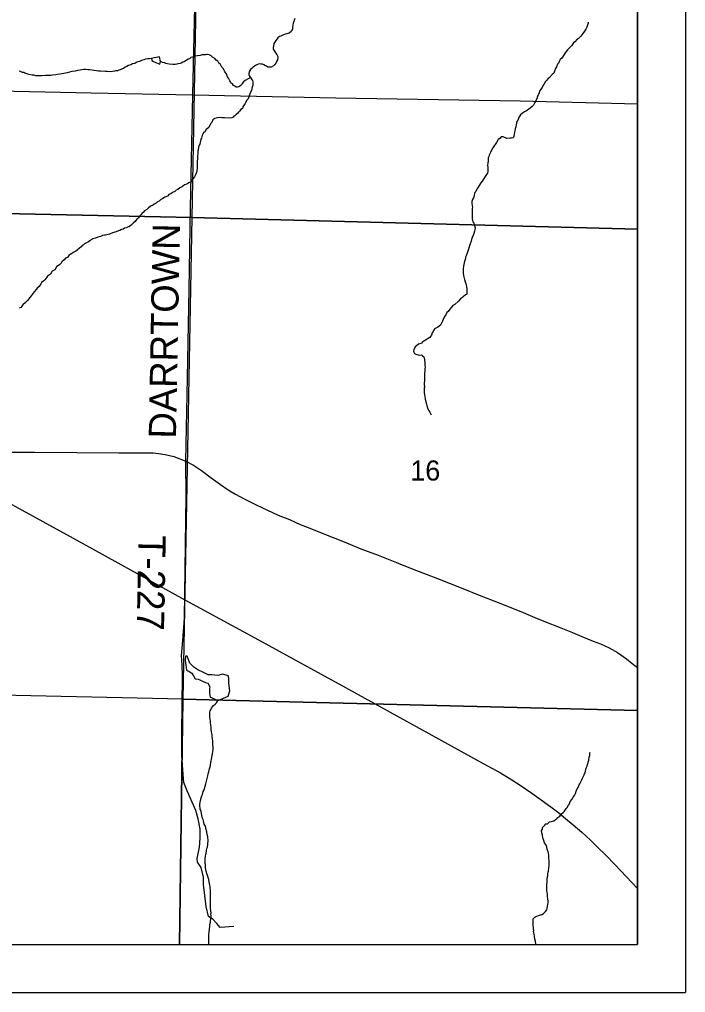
# Model space of a CAD drawing. Extents: x 0 to 34, y 0 to 22.
# Drawn here: x 7.614 to 9, y 14 to 16.024 of the extents above; entities that cross this region are included whole.
import ezdxf

# ---------------------------------------------------------------- set-up
doc = ezdxf.new("R2010")
doc.units = 0
for name, color, linetype in [('Default', 7, 'Continuous'), ('GM_X_County_Road', 7, 'Continuous'), ('GM_X_Minor_River', 7, 'Continuous'), ('GM_X_Rail_Line', 7, 'Continuous'), ('GM_X_Section', 7, 'Continuous'), ('GM_X_Section_Text', 7, 'Continuous'), ('GM_X_State_Route', 7, 'Continuous'), ('GM_X_Township_Road', 7, 'Continuous'), ('GM_X_Township_Road_Text', 7, 'Continuous'), ('SH_Data', 7, 'Continuous')]:
    doc.layers.add(name, color=color, linetype=linetype)

msp = doc.modelspace()

# ---------------------------------------------------------------- linework, layer by layer
at = {"layer": 'Default'}
for points in [[(5.898, 14.1), (8.9, 14.1), (8.9, 17.6104), (8.0065, 17.6245), (7.0308, 17.6406), (6.9889, 17.643), (5.9893, 17.6676), (5.9888, 17.6433), (5.9796, 17.2537), (5.9756, 17.0812), (5.9658, 16.6637), (5.9579, 16.0817), (5.9546, 15.9939), (5.9496, 15.8622), (5.9475, 15.8049), (5.945, 15.7379), (5.9423, 15.6675), (5.9419, 15.65), (5.9251, 14.9951), (5.9162, 14.6505)], [(8.9, 15.5877), (8.9, 16.5944), (7.9916, 16.6192), (7.9729, 15.6119)], [(8.9, 14.587), (8.9, 15.5877), (7.9729, 15.6119), (7.9542, 14.61)], [(6.9613, 14.1), (7.9469, 14.1), (7.9542, 14.61), (6.9732, 14.6315)], [(7.9469, 14.1), (8.9, 14.1), (8.9, 14.587), (7.9542, 14.61)]]:
    msp.add_lwpolyline(points, close=True, dxfattribs=at)
at = {"layer": 'GM_X_County_Road'}
msp.add_lwpolyline([(6.7323, 15.8976), (6.7874, 15.896), (6.8287, 15.8947), (6.9536, 15.8914), (6.9998, 15.8902), (7.2608, 15.882), (7.474, 15.8776), (7.7629, 15.8716), (7.9749, 15.8672), (8.2725, 15.8609), (8.656, 15.8552), (8.9, 15.8485)], dxfattribs=at)
at = {"layer": 'GM_X_Minor_River'}
for points in [[(8.1871, 16.0264), (8.1855, 16.023), (8.1847, 16.0196), (8.1834, 16.0162), (8.183, 16.0121), (8.1821, 16.0083), (8.182, 16.0041), (8.1804, 16.0019), (8.1792, 15.9992), (8.1754, 15.9959), (8.1727, 15.9948), (8.1704, 15.9941), (8.1669, 15.9935), (8.1635, 15.992), (8.1581, 15.9891), (8.155, 15.9884), (8.1519, 15.9862), (8.1504, 15.984), (8.1473, 15.9807), (8.1456, 15.9769), (8.1433, 15.9743), (8.1424, 15.969), (8.142, 15.9656), (8.1419, 15.9626), (8.1434, 15.9602), (8.1444, 15.9579), (8.147, 15.9544), (8.1492, 15.951), (8.1514, 15.9471), (8.1517, 15.9448), (8.1509, 15.9399), (8.1489, 15.9369), (8.1477, 15.9332), (8.1453, 15.9302), (8.1426, 15.9276), (8.138, 15.925), (8.1357, 15.9247), (8.1311, 15.9252), (8.1281, 15.9272), (8.1259, 15.9276), (8.1225, 15.9296), (8.1199, 15.9312), (8.1165, 15.9313), (8.113, 15.9317), (8.1096, 15.9307), (8.1054, 15.9285), (8.103, 15.9267), (8.1, 15.9252), (8.0972, 15.9219), (8.0949, 15.92), (8.0929, 15.9167), (8.0913, 15.9118), (8.0912, 15.9095), (8.0927, 15.906), (8.0949, 15.9033), (8.0971, 15.9002), (8.0986, 15.8975), (8.0992, 15.8941), (8.0995, 15.8903), (8.0995, 15.8876), (8.099, 15.8853), (8.0978, 15.8812), (8.0969, 15.8763), (8.0942, 15.8718), (8.0921, 15.8654), (8.0901, 15.8593), (8.0866, 15.8553), (8.085, 15.8523), (8.0838, 15.8492), (8.0818, 15.8466), (8.0787, 15.8422), (8.0782, 15.8391), (8.0747, 15.8366), (8.0716, 15.8332), (8.07, 15.831), (8.0673, 15.8288), (8.0646, 15.8265), (8.0623, 15.8239), (8.06, 15.8229), (8.0584, 15.8206), (8.0557, 15.8195), (8.0519, 15.8189), (8.0409, 15.8192), (8.0378, 15.8196), (8.0348, 15.8197), (8.0317, 15.8201), (8.026, 15.8195), (8.0203, 15.8181), (8.0164, 15.8152), (8.014, 15.8099), (8.0113, 15.807), (8.0077, 15.7991), (8.0023, 15.7954), (7.9995, 15.7905), (7.9968, 15.7891), (7.9956, 15.7853), (7.994, 15.7827), (7.9927, 15.7774), (7.9915, 15.7752)], [(8.7976, 16.0185), (8.7976, 16.0162), (8.7955, 16.0102), (8.7944, 16.0079), (8.7927, 16.0042), (8.79, 15.9997), (8.7865, 15.9952), (8.7845, 15.9922), (8.7818, 15.9896), (8.7771, 15.9844), (8.7748, 15.9829), (8.7697, 15.9774), (8.7666, 15.9756), (8.7627, 15.9696), (8.7545, 15.9607), (8.7498, 15.9547), (8.7474, 15.9513), (8.7427, 15.9435), (8.7392, 15.9409), (8.7376, 15.9383), (8.736, 15.9341), (8.7333, 15.9312), (8.7312, 15.9255), (8.7292, 15.9221), (8.7276, 15.9165), (8.726, 15.9127), (8.7225, 15.9098), (8.7163, 15.9027), (8.7139, 15.9012), (8.7104, 15.8975), (8.7089, 15.8953), (8.7049, 15.8889), (8.7033, 15.8863), (8.7017, 15.8826), (8.697, 15.8762), (8.6954, 15.8717), (8.6934, 15.8668), (8.6914, 15.8631), (8.6909, 15.8608), (8.6882, 15.8552), (8.6858, 15.8499), (8.6838, 15.8461), (8.681, 15.8428), (8.6768, 15.8395), (8.6714, 15.8354), (8.669, 15.8344), (8.6648, 15.8318), (8.6609, 15.8292), (8.6563, 15.8255), (8.6535, 15.8218), (8.6507, 15.8147), (8.6491, 15.8117), (8.6479, 15.8087), (8.6475, 15.8052), (8.6466, 15.8007), (8.6457, 15.7965), (8.6449, 15.7928), (8.6444, 15.7897), (8.6436, 15.7852), (8.6427, 15.7814), (8.6411, 15.778), (8.6377, 15.777), (8.635, 15.7771), (8.6282, 15.7768), (8.6202, 15.7797), (8.6161, 15.7802), (8.6133, 15.7768), (8.6099, 15.7743), (8.6063, 15.7679), (8.5992, 15.7574), (8.596, 15.7522), (8.5944, 15.7473), (8.5924, 15.7447), (8.5912, 15.742), (8.5904, 15.739), (8.5896, 15.7364), (8.5891, 15.7322), (8.5891, 15.7299), (8.5886, 15.725), (8.5881, 15.7212), (8.5884, 15.7163), (8.5887, 15.7132), (8.5886, 15.7087), (8.5877, 15.7045), (8.5861, 15.7019), (8.5818, 15.6952), (8.5779, 15.6899), (8.5727, 15.6821), (8.5684, 15.6754), (8.5661, 15.6724), (8.5633, 15.6664), (8.5613, 15.6641), (8.5609, 15.6619), (8.56, 15.6581), (8.5588, 15.6532), (8.5568, 15.6498), (8.5552, 15.6457), (8.5551, 15.6422), (8.5561, 15.6365), (8.5564, 15.6335), (8.556, 15.6308)], [(8.0949, 15.9033), (8.0834, 15.8975), (8.0802, 15.8942), (8.0775, 15.8912), (8.0759, 15.8882), (8.0728, 15.8856), (8.0701, 15.8838), (8.0674, 15.8835), (8.0652, 15.8835), (8.0622, 15.8855), (8.0595, 15.8867), (8.057, 15.8906), (8.0547, 15.8918), (8.0532, 15.8945), (8.0514, 15.8968), (8.0492, 15.9022), (8.047, 15.9049), (8.0445, 15.9114), (8.0412, 15.9149), (8.0383, 15.9218), (8.0349, 15.9246), (8.0324, 15.9303), (8.029, 15.9331), (8.0265, 15.9373), (8.0231, 15.9393), (8.0205, 15.9431), (8.0153, 15.9459), (8.013, 15.9487), (8.0089, 15.9503), (8.0055, 15.9511), (8.0032, 15.9512), (8.0009, 15.9509), (7.9986, 15.9509), (7.9941, 15.9503), (7.9902, 15.9492), (7.9841, 15.9482), (7.9799, 15.948), (7.9776, 15.9472), (7.9742, 15.9458), (7.9707, 15.9448), (7.968, 15.9425), (7.965, 15.9415), (7.9622, 15.9393), (7.9592, 15.9378), (7.9565, 15.936), (7.9538, 15.9353), (7.9503, 15.9335), (7.948, 15.9328), (7.9438, 15.9317), (7.9415, 15.9314), (7.9381, 15.9308), (7.9358, 15.9308), (7.9331, 15.9305), (7.9256, 15.9314), (7.9221, 15.9319), (7.9184, 15.9328), (7.9157, 15.9336), (7.9116, 15.9344), (7.9089, 15.936), (7.9073, 15.9364)], [(7.8885, 15.9431), (7.8844, 15.9423), (7.8809, 15.942), (7.8764, 15.9414), (7.8729, 15.94), (7.8679, 15.9389), (7.8637, 15.9364), (7.858, 15.9354), (7.8537, 15.9328), (7.8488, 15.9322), (7.8457, 15.93), (7.8411, 15.9286), (7.8376, 15.926), (7.8338, 15.9246), (7.8303, 15.922), (7.8264, 15.9206), (7.8237, 15.9191), (7.8207, 15.9185), (7.8176, 15.9174), (7.8138, 15.9171), (7.8115, 15.9164), (7.8077, 15.9157), (7.8035, 15.9155), (7.7963, 15.9156), (7.7921, 15.9161), (7.7826, 15.9164), (7.7781, 15.9169), (7.7739, 15.9173), (7.7686, 15.9179), (7.7652, 15.9187), (7.7599, 15.9192), (7.7561, 15.9197), (7.7511, 15.9198), (7.7477, 15.9199)], [(7.9073, 15.9364), (7.9052, 15.9463), (7.8987, 15.9452), (7.8942, 15.9446), (7.8885, 15.9431), (7.8891, 15.9389), (7.8929, 15.9366)], [(7.8929, 15.9366), (7.8989, 15.9338), (7.9061, 15.9314), (7.9073, 15.9364)], [(7.7477, 15.9199), (7.7435, 15.9196), (7.7401, 15.9189), (7.7344, 15.9183), (7.7297, 15.9165), (7.7229, 15.9156), (7.7133, 15.9131), (7.7095, 15.9125), (7.7026, 15.9111), (7.6988, 15.9105), (7.6927, 15.9095), (7.6893, 15.9092), (7.6828, 15.9082), (7.6794, 15.9079), (7.671, 15.9077), (7.6683, 15.9074), (7.6607, 15.9072), (7.6573, 15.9069), (7.6482, 15.9072), (7.644, 15.908), (7.6402, 15.9085), (7.6372, 15.9089), (7.6334, 15.9098), (7.6289, 15.9114), (7.6251, 15.9123), (7.6228, 15.9135), (7.6202, 15.9139), (7.6164, 15.9159), (7.613, 15.9164)], [(7.9915, 15.7752), (7.989, 15.765), (7.9878, 15.7627), (7.9866, 15.7582), (7.9857, 15.7521), (7.9853, 15.7499), (7.9848, 15.7457), (7.9846, 15.7388), (7.9841, 15.7339), (7.984, 15.7297), (7.9836, 15.7271), (7.9835, 15.7233), (7.9838, 15.7206), (7.9837, 15.7134), (7.9832, 15.7104), (7.9823, 15.7058), (7.9811, 15.7021), (7.9783, 15.6968), (7.9748, 15.6923), (7.9709, 15.6867), (7.9663, 15.6846), (7.9624, 15.6816), (7.9574, 15.6799), (7.9528, 15.6762), (7.9474, 15.674), (7.9435, 15.6703), (7.94, 15.6689), (7.9369, 15.6663), (7.9323, 15.6645), (7.9288, 15.6616), (7.925, 15.6601), (7.9219, 15.6568), (7.9161, 15.6547), (7.9119, 15.651), (7.908, 15.6495), (7.9045, 15.6462), (7.9011, 15.6448), (7.8984, 15.6418), (7.8941, 15.64), (7.891, 15.6374), (7.8883, 15.6367), (7.8822, 15.6323), (7.8787, 15.6286), (7.874, 15.6261), (7.8713, 15.6227), (7.869, 15.6212), (7.8674, 15.6182), (7.8643, 15.6157), (7.8615, 15.6108), (7.8576, 15.6082), (7.8545, 15.6037), (7.8502, 15.6004), (7.8463, 15.5963), (7.8436, 15.5945), (7.8413, 15.5931), (7.8386, 15.592), (7.8359, 15.5905), (7.8325, 15.5899), (7.8294, 15.588), (7.826, 15.587), (7.8229, 15.5855), (7.8202, 15.5848), (7.8148, 15.5823), (7.8072, 15.5802), (7.801, 15.5773), (7.7957, 15.5763), (7.793, 15.5756), (7.7907, 15.5753), (7.7865, 15.5746), (7.7823, 15.5725), (7.7773, 15.5715), (7.7723, 15.5689), (7.7666, 15.5679), (7.7604, 15.5639), (7.7577, 15.5617), (7.7492, 15.5573), (7.7469, 15.5555), (7.7446, 15.554), (7.7422, 15.551), (7.7388, 15.5481), (7.7341, 15.5444), (7.7314, 15.5422), (7.7283, 15.5411), (7.726, 15.5397), (7.7225, 15.5367), (7.7198, 15.5356), (7.7164, 15.5331), (7.7136, 15.5293), (7.7098, 15.5275), (7.707, 15.5238), (7.7024, 15.5201), (7.7008, 15.5175), (7.698, 15.5141), (7.6911, 15.5097), (7.6872, 15.5034), (7.6818, 15.5005), (7.6782, 15.4941), (7.6724, 15.4901), (7.6712, 15.4878), (7.6669, 15.4822), (7.6646, 15.4808)], [(8.556, 15.6308), (8.5563, 15.627), (8.556, 15.6141), (8.5562, 15.6092), (8.5569, 15.6061), (8.5576, 15.6034), (8.5591, 15.6003), (8.5602, 15.5977), (8.5609, 15.5954), (8.5619, 15.5904), (8.5614, 15.5866), (8.561, 15.5836), (8.5597, 15.579), (8.5581, 15.5749), (8.5569, 15.5727), (8.5561, 15.5704), (8.5549, 15.5662), (8.5537, 15.5632), (8.552, 15.5572), (8.55, 15.5512), (8.5475, 15.5444), (8.5463, 15.5399), (8.5438, 15.5327), (8.5422, 15.5297), (8.5418, 15.527), (8.5409, 15.5229), (8.5393, 15.5176), (8.5389, 15.5146), (8.538, 15.5112), (8.5375, 15.5055), (8.5373, 15.4968), (8.5379, 15.4914), (8.5383, 15.4891), (8.54, 15.4834), (8.5414, 15.4784), (8.5432, 15.4727), (8.5442, 15.4673), (8.5449, 15.4635), (8.5449, 15.4612), (8.5451, 15.4574), (8.5451, 15.4551), (8.5447, 15.4529), (8.5423, 15.451), (8.5373, 15.447), (8.5338, 15.4444), (8.5315, 15.4429), (8.5272, 15.4381), (8.5198, 15.4314), (8.516, 15.4292), (8.5132, 15.4255), (8.5097, 15.4218), (8.5062, 15.4166), (8.5035, 15.4144), (8.5015, 15.4098), (8.4987, 15.4061), (8.4959, 15.3997), (8.4939, 15.3964), (8.4919, 15.3922), (8.4903, 15.3885), (8.4872, 15.3859), (8.4837, 15.3833), (8.4807, 15.3822), (8.4784, 15.3815), (8.4752, 15.3771), (8.4748, 15.3748), (8.4728, 15.3722), (8.4712, 15.3677), (8.4693, 15.365), (8.4677, 15.3628), (8.4646, 15.3602), (8.4623, 15.3591), (8.4588, 15.3569), (8.4557, 15.3547), (8.4526, 15.3537), (8.4503, 15.3511), (8.4468, 15.3496), (8.4445, 15.3485), (8.4403, 15.3452), (8.4376, 15.343), (8.4344, 15.337), (8.4339, 15.3344), (8.4343, 15.3321), (8.4361, 15.3294), (8.4384, 15.3278), (8.441, 15.327), (8.4433, 15.3262), (8.4459, 15.3261), (8.4505, 15.3264), (8.4527, 15.3244), (8.4557, 15.3224), (8.4571, 15.3167), (8.4571, 15.3144), (8.4578, 15.3114), (8.4576, 15.3045), (8.4579, 15.3015), (8.4574, 15.2973), (8.4573, 15.2935), (8.4568, 15.2867), (8.4565, 15.2745), (8.4563, 15.2658), (8.4566, 15.2593)], [(7.6646, 15.4808), (7.6599, 15.4767), (7.6583, 15.4745), (7.6548, 15.4688), (7.6505, 15.4655), (7.6497, 15.4629), (7.6446, 15.4573), (7.6423, 15.4551), (7.6384, 15.4495), (7.6356, 15.4461), (7.6305, 15.4394), (7.6266, 15.4353), (7.6212, 15.4302), (7.6169, 15.4253), (7.6131, 15.4235)], [(8.4566, 15.2593), (8.4561, 15.257), (8.4564, 15.2521), (8.4563, 15.2472), (8.4566, 15.2441), (8.4573, 15.2399), (8.4583, 15.2342), (8.4593, 15.2292), (8.46, 15.2262), (8.4607, 15.2239), (8.4614, 15.2212), (8.4628, 15.2166), (8.465, 15.2116), (8.4683, 15.2062), (8.4705, 15.2019)], [(8.0273, 14.6077), (8.0481, 14.6164), (8.0517, 14.6274), (8.0494, 14.6438), (8.0496, 14.654), (8.0482, 14.659), (8.0369, 14.6623), (8.0266, 14.6598), (8.0141, 14.6609), (8.0068, 14.6606), (7.9952, 14.6666), (7.985, 14.6713), (7.9768, 14.6768), (7.9686, 14.6854), (7.9653, 14.6942), (7.9632, 14.6999), (7.9594, 14.6996), (7.9588, 14.6909), (7.9598, 14.6814), (7.9618, 14.6707), (7.9671, 14.6675), (7.9727, 14.6644), (7.976, 14.6586), (7.9793, 14.6528)], [(7.9793, 14.6528), (7.9857, 14.6516), (7.9895, 14.6503), (7.9963, 14.6472), (8.0008, 14.6452), (8.0061, 14.6432), (8.0101, 14.6362), (8.0093, 14.6317), (8.0095, 14.6229), (8.0108, 14.6142), (8.0146, 14.6129), (8.0247, 14.6082), (8.0273, 14.6077)], [(8.0115, 14.4729), (8.0124, 14.4789), (8.0128, 14.4812), (8.0137, 14.4854), (8.0145, 14.4888), (8.015, 14.4937), (8.0158, 14.496), (8.0163, 14.5016), (8.0168, 14.5054), (8.0169, 14.5111), (8.0166, 14.5142), (8.0164, 14.5195), (8.0161, 14.5241), (8.0158, 14.5271), (8.0152, 14.534), (8.0149, 14.5363), (8.0142, 14.5389), (8.0135, 14.5431), (8.0128, 14.5466), (8.0125, 14.5504), (8.0123, 14.5572), (8.0116, 14.5603), (8.0113, 14.5637), (8.0107, 14.5694), (8.0104, 14.5725), (8.01, 14.5748), (8.0102, 14.5831), (8.011, 14.5858), (8.0119, 14.588), (8.0138, 14.5918), (8.0178, 14.597), (8.0213, 14.6), (8.024, 14.6029), (8.026, 14.6059), (8.0273, 14.6077)], [(8.7636, 14.4013), (8.766, 14.4062), (8.7688, 14.4099), (8.77, 14.4129), (8.7716, 14.4155), (8.7724, 14.4186), (8.7744, 14.4235), (8.7768, 14.4268), (8.7784, 14.4317), (8.7803, 14.4343), (8.7815, 14.437), (8.7828, 14.44), (8.784, 14.4422), (8.7848, 14.4445), (8.786, 14.4475), (8.7888, 14.4527), (8.7896, 14.455), (8.7908, 14.4573), (8.7916, 14.4603), (8.7933, 14.4667), (8.7953, 14.4708), (8.7957, 14.4742), (8.7965, 14.4765), (8.7978, 14.481), (8.7986, 14.4833), (8.7995, 14.4894), (8.8007, 14.4931), (8.8008, 14.4977), (8.8012, 14.5)], [(8.0079, 14.1), (8.0081, 14.1092), (8.0079, 14.1172), (8.008, 14.1206), (8.0085, 14.1259), (8.0094, 14.1309), (8.0099, 14.1388), (8.0104, 14.1418), (8.0112, 14.1464), (8.0122, 14.1555), (8.0127, 14.1593), (8.0124, 14.1635), (8.0125, 14.1661), (8.0121, 14.1692), (8.0115, 14.176), (8.0112, 14.1795), (8.0115, 14.1901), (8.0112, 14.1931), (8.0115, 14.2083), (8.0112, 14.2106), (8.0113, 14.2137), (8.011, 14.2167), (8.0107, 14.2205), (8.0103, 14.2236), (8.0097, 14.2266), (8.0086, 14.2304), (8.0079, 14.235), (8.0065, 14.2396), (8.0055, 14.2434), (8.004, 14.2473), (8.0023, 14.2523), (8.0016, 14.2557), (8.0009, 14.2595), (8.0007, 14.2664), (8.0004, 14.2687), (8.0001, 14.2728), (8.0006, 14.2778), (8.0011, 14.2842), (8.0015, 14.2869), (8.0024, 14.2895), (8.0029, 14.2952), (8.0041, 14.2994), (8.0049, 14.3024), (8.0058, 14.3077), (8.0059, 14.31), (8.0064, 14.3156), (8.0058, 14.324), (8.0048, 14.3286), (8.0041, 14.3343), (8.0023, 14.3389), (8.001, 14.3458), (7.998, 14.3504), (7.9967, 14.3573), (7.996, 14.36), (7.9942, 14.3638), (7.9929, 14.373), (7.9918, 14.3768), (7.99, 14.3814), (7.9894, 14.3894), (7.9891, 14.3921), (7.9896, 14.3951), (7.9904, 14.3997), (7.9929, 14.4068), (7.9933, 14.4091), (7.9945, 14.4117), (7.9962, 14.4181), (7.9982, 14.4219), (8.0002, 14.4294), (8.0015, 14.4344), (8.0028, 14.44), (8.004, 14.4427), (8.0061, 14.451), (8.0065, 14.4548), (8.0081, 14.4589), (8.009, 14.4631), (8.0107, 14.4695), (8.0115, 14.4729)], [(8.6888, 14.1), (8.6887, 14.1006), (8.688, 14.1067), (8.6866, 14.1113), (8.686, 14.117), (8.6849, 14.1212), (8.6846, 14.1243), (8.6839, 14.1269), (8.684, 14.1292), (8.6833, 14.1327), (8.6831, 14.1414), (8.6828, 14.1441), (8.6829, 14.1475), (8.6826, 14.1509), (8.683, 14.1532), (8.6865, 14.1569), (8.6888, 14.1584), (8.6927, 14.1598), (8.6958, 14.1612), (8.6984, 14.1615), (8.7007, 14.1623), (8.7042, 14.1644), (8.7085, 14.1685), (8.7112, 14.1719), (8.712, 14.1745), (8.7129, 14.1794), (8.7134, 14.1832), (8.7138, 14.1874), (8.7139, 14.19), (8.7136, 14.195), (8.713, 14.2), (8.7124, 14.2053), (8.7117, 14.2084), (8.7114, 14.2122), (8.7114, 14.2152), (8.7112, 14.2194), (8.7116, 14.2224), (8.7118, 14.2319), (8.7123, 14.238), (8.7132, 14.2429), (8.7137, 14.2475), (8.7141, 14.2501), (8.7146, 14.2524), (8.7155, 14.2592), (8.716, 14.2634), (8.7161, 14.2687), (8.7159, 14.2755), (8.7155, 14.2782), (8.7153, 14.282), (8.7153, 14.2858), (8.7147, 14.2896), (8.714, 14.2927), (8.7122, 14.298), (8.7105, 14.3061), (8.7086, 14.3084), (8.7064, 14.3111), (8.705, 14.3165), (8.7028, 14.3215), (8.7022, 14.3276), (8.7008, 14.3318), (8.7005, 14.336), (8.7021, 14.3397), (8.7026, 14.3435), (8.7073, 14.348), (8.7096, 14.3506), (8.7127, 14.3512), (8.7169, 14.3549), (8.7211, 14.356), (8.7257, 14.3574), (8.7292, 14.3596), (8.7323, 14.3614), (8.7342, 14.364), (8.7385, 14.3666), (8.7409, 14.3707), (8.7451, 14.3744), (8.7479, 14.3774), (8.7514, 14.3826), (8.7534, 14.3848), (8.7565, 14.3897), (8.7585, 14.3927), (8.7601, 14.3976), (8.7636, 14.4013)]]:
    msp.add_lwpolyline(points, dxfattribs=at)
at = {"layer": 'GM_X_Rail_Line'}
msp.add_lwpolyline([(7.5481, 15.0419), (7.6194, 15.0032), (7.7191, 14.9486), (7.9583, 14.8172), (8.1034, 14.7375), (8.2925, 14.6342), (8.5789, 14.4766), (8.6146, 14.4567), (8.6386, 14.4421), (8.6581, 14.4297), (8.6798, 14.415), (8.7041, 14.3977), (8.7227, 14.3839), (8.7362, 14.3737), (8.7502, 14.3622), (8.7661, 14.3488), (8.7841, 14.3335), (8.802, 14.3169), (8.8171, 14.3026), (8.8337, 14.2862), (8.8536, 14.2657), (8.9, 14.2167)], dxfattribs=at)
at = {"layer": 'GM_X_Section'}
for points in [[(7.0136, 16.6391), (7.9916, 16.6192), (7.9729, 15.6119), (6.9929, 15.633)], [(7.9729, 15.6119), (7.9542, 14.61), (6.9732, 14.6315), (6.9929, 15.633)]]:
    msp.add_lwpolyline(points, close=True, dxfattribs=at)
at = {"layer": 'GM_X_State_Route'}
msp.add_lwpolyline([(7.5729, 15.1241), (7.6457, 15.1237), (7.8208, 15.1228), (7.8707, 15.1229), (7.8921, 15.1226), (7.9031, 15.1214), (7.9173, 15.1193), (7.935, 15.1148), (7.9603, 15.1054), (7.976, 15.097), (7.9926, 15.0857), (8.0131, 15.0705), (8.0325, 15.0568), (8.0484, 15.0454), (8.0634, 15.0367), (8.0816, 15.0273), (8.1067, 15.0147), (8.1301, 15.0033), (8.1523, 14.9929), (8.1757, 14.9837), (8.198, 14.9737), (8.2182, 14.966), (8.2471, 14.9541), (8.2863, 14.9387), (8.3245, 14.9232), (8.3607, 14.9098), (8.3985, 14.8944), (8.4313, 14.8813), (8.4837, 14.8611), (8.5363, 14.8401), (8.5704, 14.8268), (8.6103, 14.811), (8.6574, 14.7923), (8.6867, 14.7803), (8.705, 14.7726), (8.7406, 14.7584), (8.7649, 14.7486), (8.7839, 14.7406), (8.808, 14.7312), (8.8233, 14.7253), (8.841, 14.7173), (8.8581, 14.7073), (8.877, 14.6943), (8.8888, 14.6844), (8.9, 14.6758)], dxfattribs=at)
at = {"layer": 'GM_X_Township_Road'}
for points in [[(7.9603, 15.1054), (7.9633, 15.279), (7.9669, 15.4627), (7.97, 15.632), (7.9749, 15.8672), (7.978, 16.0209), (7.9897, 16.4938), (8.0006, 17.1268), (8.0031, 17.3329), (8.0067, 17.6239), (8.0043, 17.626)], [(8.0603, 14.1375), (8.0317, 14.135), (8.0243, 14.1439), (8.0157, 14.1532), (8.0071, 14.1583), (8.0022, 14.1786), (7.9967, 14.2248), (7.997, 14.2399), (7.9922, 14.2602), (7.9841, 14.2711), (7.9838, 14.279), (7.9888, 14.3023), (7.9901, 14.3214), (7.9897, 14.3396), (7.9856, 14.3616), (7.981, 14.3784), (7.963, 14.4196), (7.9563, 14.4368), (7.9546, 14.4537), (7.9521, 14.4936), (7.9519, 14.5385), (7.9534, 14.6585), (7.9522, 14.6807), (7.9508, 14.7006), (7.9536, 14.7322), (7.9571, 14.7789), (7.961, 15.0325), (7.9603, 15.1054)]]:
    msp.add_lwpolyline(points, dxfattribs=at)
at = {"layer": 'SH_Data'}
for p, q in [((9, 21), (9, 14)), ((8.9, 20.9), (8.9, 14.1)), ((2.1, 14.1), (8.9, 14.1)), ((2, 14), (9, 14))]:
    msp.add_line(p, q, dxfattribs=at)

# ---------------------------------------------------------------- texts
at = {"layer": 'GM_X_Section_Text'}
msp.add_text('16', height=0.04186, rotation=0, dxfattribs=at).set_placement((8.4273, 15.065))
at = {"layer": 'GM_X_Township_Road_Text'}
for s, rotation, p in [('DARRTOWN', 88.9279, (7.9396, 15.1519)), ('T-227', 268.882, (7.8617, 14.9518))]:
    msp.add_text(s, height=0.05682, rotation=rotation, dxfattribs=at).set_placement(p)

doc.saveas('drawing.dxf')
